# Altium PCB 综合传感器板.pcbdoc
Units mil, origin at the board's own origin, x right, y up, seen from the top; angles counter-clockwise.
Board outline 1885 x 1295 mil, 2 copper layers (Top Layer, Bottom Layer); 21 components, 15 nets, 74 pads, 12 vias.
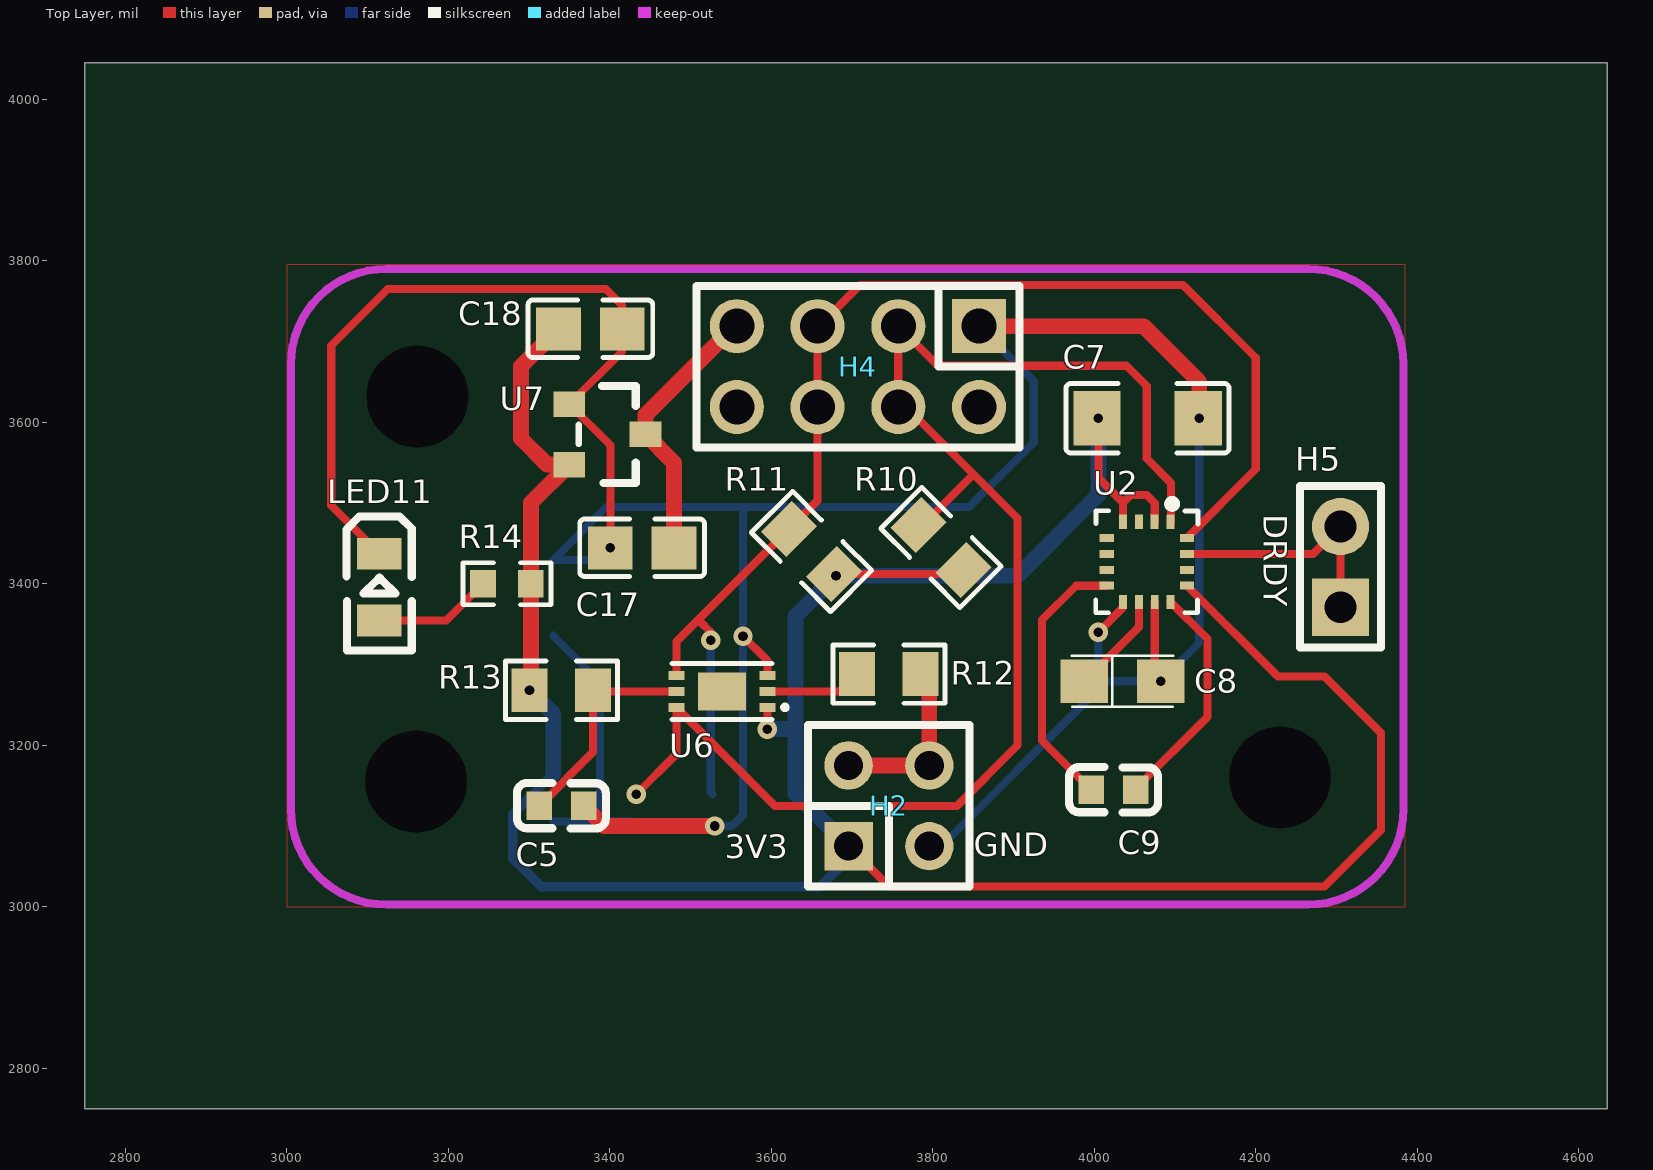
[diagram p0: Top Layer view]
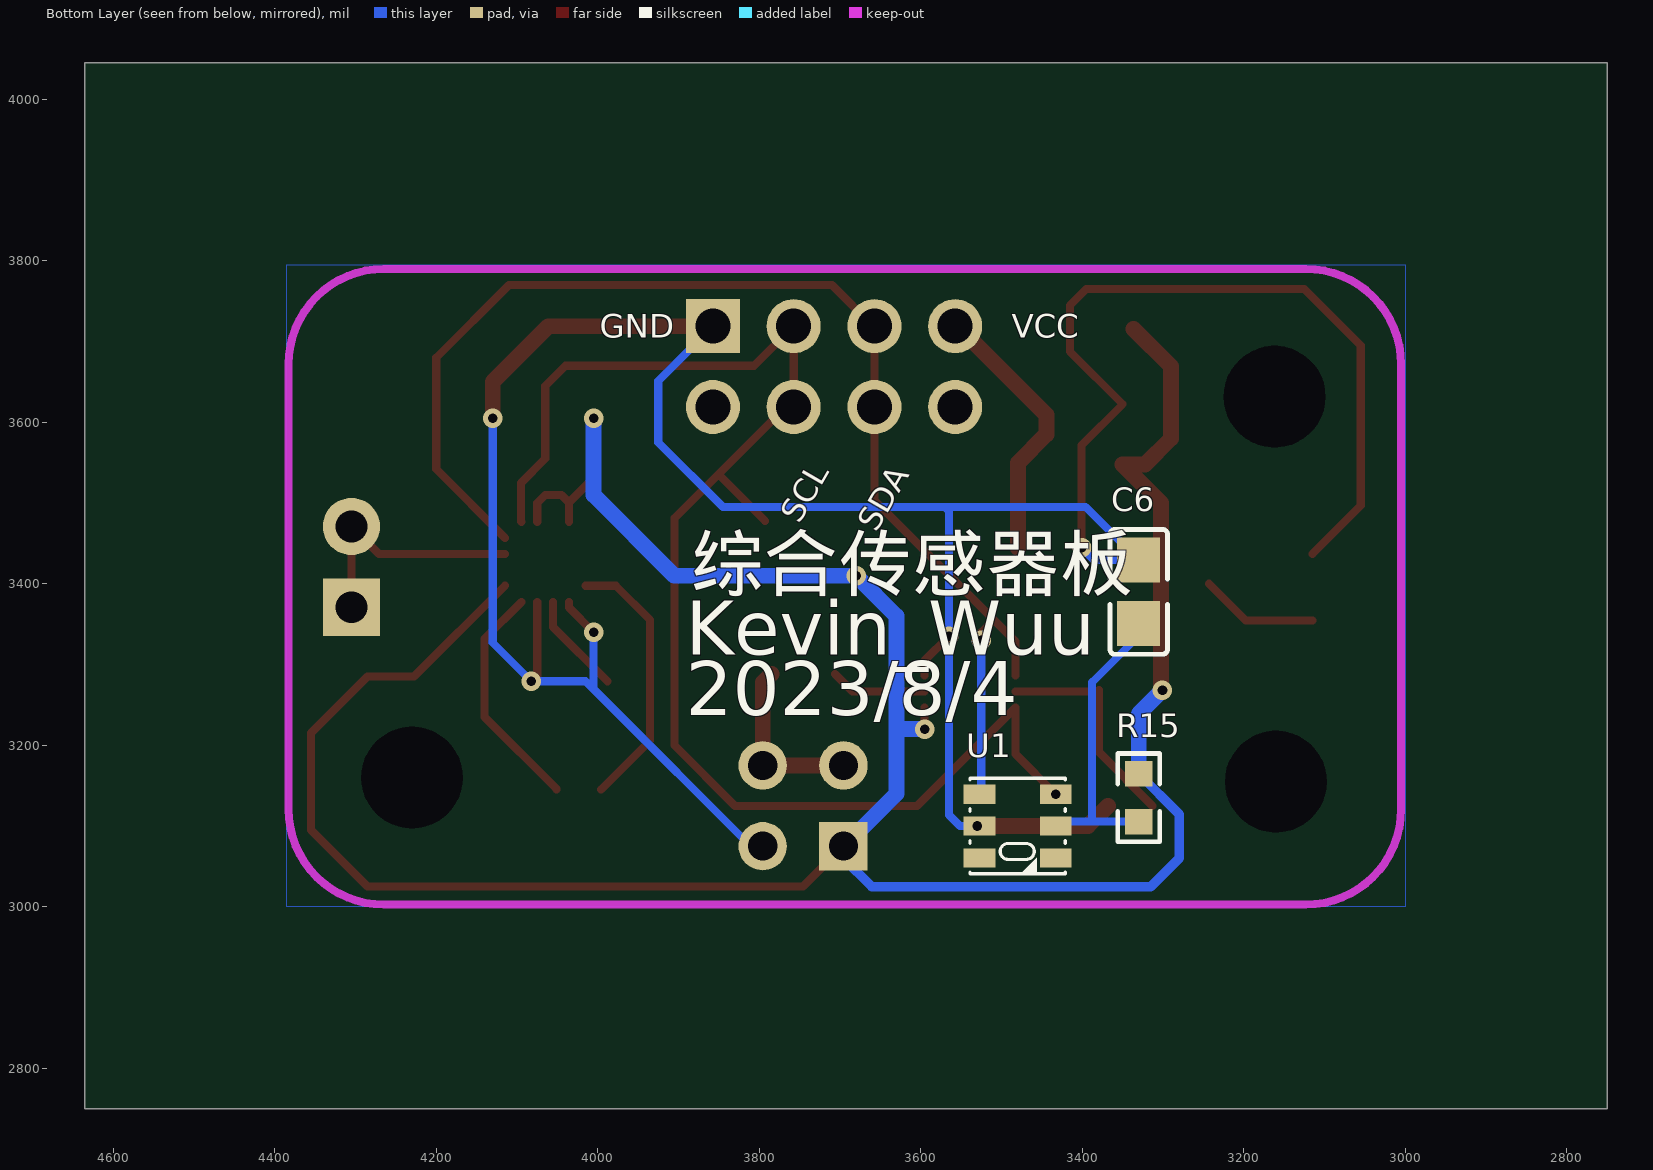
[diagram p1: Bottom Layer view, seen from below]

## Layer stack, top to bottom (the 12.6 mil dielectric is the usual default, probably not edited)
Top Layer: signal copper (thickness not stored)
Dielectric: dielectric 12.6, FR-4, Dk 4.8
Bottom Layer: signal copper (thickness not stored)

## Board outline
4635,2750 2750,2750 2750,4045 4635,4045
cut-out: 4292.99,3160 ccw(c4230,3160) 4167.01,3160 ccw(c4230,3160)
cut-out: 3222.99,3155 ccw(c3160,3155) 3097.01,3155 ccw(c3160,3155)
cut-out: 3224.74,3631.73 ccw(c3161.75,3631.73) 3098.76,3631.73 ccw(c3161.75,3631.73)

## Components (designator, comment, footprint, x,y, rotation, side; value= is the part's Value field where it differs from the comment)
C5 "CC0603KRX7R9BB104" C0603 3340.3,3125 r0 top
C6 "GRM21BR61H106KE43L" C0805 3330,3390 r90 bottom
C7 "1206B104K500AT" C1206 4065.99,3605 r0 top
C8 "TAJA475K016RNJ" CASE-A_3216 4035,3279.27 r0 top
C9 "CL10B224KA8NNNC" C0603 4023.55,3145 r180 top
C17 "CL21B105KBFNNNE" C0805 3440,3444.53 r180 top
C18 "CL21B105KBFNNNE" C0805 3375.94,3715.75 r0 top
H2 "HDR-M_2.54_2x2" HDR-TH_4P-P2.54-V-M-R2-C2-S2.54-1 3745.63,3125 r0 top
H4 "HDR-M_2.54_2x4" HDR-TH_8P-P2.54-V-M-R2-C4-S2.54 3707.24,3668.98 r180 top
H5 "HDR-M_2.54_1x2P" HDR-TH_2P-P2.54-V-M-1 4305,3420.99 r90 top
LED11 "NCD0805B2" LED0805-R-RD 3114.73,3395.8 r270 top
R10 "0805W8F4701T5E" R0805 3810,3445 r315 top
R11 "0805W8F4701T5E" R0805 3649.79,3440 r135 top
R12 "RMCF0805FT10K0" R0805 3745.63,3288.21 r0 top
R13 "0805W8F1001T5E" R0805 3340,3268.22 r180 top
R14 "0603WAF100KT5E" R0603 3272.62,3400 r0 top
R15 "0603WAF3600T5E" R0603 3330,3135.12 r270 bottom
U1 "AHT20-F" SENSOR-SMD-6_AHT20 3480,3100 r0 bottom
U2 "QMC5883L" LGA-16_L3.0-W3.0-P0.50-BL_SQ 4065,3427.15 r180 top
U6 "BH1750FVI-TR" WSOF-6_L2.6-W1.6-P0.50-TL-EP 3538.89,3266.62 r180 top
U7 "XC6206-3.3V" SSOT-3_L2.9-W1.6-P0.95-LS2.8-BR 3397.08,3585 r180 top

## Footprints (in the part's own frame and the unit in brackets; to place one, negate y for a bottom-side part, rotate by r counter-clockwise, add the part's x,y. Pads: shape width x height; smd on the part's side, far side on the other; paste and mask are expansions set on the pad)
C0603 [mm]
  rect 0.8x0.9 smd mask+0.051: 1(-0.7,0) 2(0.7,0)
  silkscreen extent -1.41,-0.71 1.39,0.72
C0805 [mm]
  rect 1.41x1.35 smd paste-100 mask+0.051: 1(-1,0) 2(1,0)
  silkscreen extent -1.96,-0.9 1.96,0.9
C1206 [mm]
  rect 1.485x1.728 smd paste-100 mask+0.051: 1(-1.593,0) 2(1.593,0)
  silkscreen extent -2.56,-1.09 2.56,1.09
CASE-A_3216 [mil]
  rect 59.05x53.5 smd mask+2.01: 1(-47.24,0) 2(47.24,0)
  silkscreen extent -63,-32 63,32
HDR-TH_2P-P2.54-V-M-1 [mm]
  rect 1.8x1.8 hole 1 mask+0.051: 1(-1.27,0)
  round 1.8 hole 1 mask+0.051: 2(1.27,0)
  silkscreen extent -2.54,-1.27 2.54,1.27
HDR-TH_4P-P2.54-V-M-R2-C2-S2.54-1 [mil]
  rect 60x60 hole 36 mask+2.01: 1(-50,-50)
  round 60 hole 36 mask+2.01: 2(-50,50) 3(50,-50) 4(50,50)
  silkscreen extent -100,-100 100,100
HDR-TH_8P-P2.54-V-M-R2-C4-S2.54 [mm]
  rect 1.7x1.7 hole 1.1 mask+0.051: 1(-3.81,-1.27)
  round 1.7 hole 1.1 mask+0.051: 2(-3.81,1.27) 3(-1.27,-1.27) 4(-1.27,1.27) 5(1.27,-1.27) 6(1.27,1.27) 7(3.81,-1.27) 8(3.81,1.27)
  silkscreen extent -5.08,-2.54 5.08,2.54
LED0805-R-RD [mm]
  rect 1x1.4 smd mask+0.051: 1(1.05,0) 2(-1.05,0)
  silkscreen extent -2.22,-1.04 1.99,1.01
LGA-16_L3.0-W3.0-P0.50-BL_SQ [mm]
  rect 0.25x0.45 smd mask+0.051: 1(-0.75,-1.263) 2(-0.25,-1.263) 3(0.25,-1.263) 4(0.75,-1.263) 9(0.75,1.263) 10(0.25,1.263) 11(-0.25,1.263) 12(-0.75,1.263)
  rect 0.45x0.25 smd mask+0.051: 5(1.263,-0.75) 6(1.263,-0.25) 7(1.263,0.25) 8(1.263,0.75) 13(-1.263,0.75) 14(-1.263,0.25) 15(-1.263,-0.25) 16(-1.263,-0.75)
  silkscreen extent -1.61,-1.95 1.61,1.6
R0603 [mil]
  rect 31.75x34.02 smd paste-3937.01 mask+2: 1(-29.66,0) 2(29.66,0)
  silkscreen extent -55,-26 55,26
R0805 [mm]
  rect 1.133x1.377 smd paste-100 mask+0.051: 1(-1,0) 2(1,0)
  silkscreen extent -1.76,-0.92 1.76,0.92
SENSOR-SMD-6_AHT20 [mm]
  rect 1x0.6 smd paste+0 mask+0.05: 1(-1.2,1) 2(-1.2,0) 3(-1.2,-1) 4(1.2,-1) 5(1.2,0) 6(1.2,1)
  silkscreen extent -1.5,-1.5 1.5,1.5
SSOT-3_L2.9-W1.6-P0.95-LS2.8-BR [mm]
  rect 1x0.8 smd mask+0.051: 1(1.2,-0.95) 2(1.2,0.95) 3(-1.2,0)
  silkscreen extent -0.89,-1.52 0.9,1.52
WSOF-6_L2.6-W1.6-P0.50-TL-EP [mm]
  rect 0.505x0.28 smd mask+0.051: 1(-1.427,0.5) 2(-1.427,0) 3(-1.427,-0.5) 4(1.427,-0.5) 5(1.427,0) 6(1.427,0.5)
  rect 1.5x1.2 smd mask+0.051: 7(0,0)
  silkscreen extent -2.05,-0.88 1.58,0.88

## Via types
v1: diameter 24.02, hole 12.01, Top Layer to Bottom Layer, 12 vias

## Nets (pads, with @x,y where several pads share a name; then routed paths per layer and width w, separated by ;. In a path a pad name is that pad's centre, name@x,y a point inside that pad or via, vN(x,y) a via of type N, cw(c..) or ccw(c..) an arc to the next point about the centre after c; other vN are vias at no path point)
$1N853: R12.1 U6.2 | length 120.1
  Top Layer w10: U6.2 3684.67,3266.61 R12.1
$1N861: C5.1 R13.1 U6.5 | length 274.8
  Top Layer w10: C5.1 3379.37,3191.62 R13.1@3379.37,3265.01 ; R13.1 R13.1@3379.37,3265.01 ; U6.5 3380.98,3266.61 R13.1@3379.37,3265.01
$1N1365: LED11.1 R14.1 | length 147.1
  Top Layer w10: LED11.1 3197.41,3354.45 R14.1
$1N1636: C6.1 R15.2 U1.2 | length 359.1
  Bottom Layer w10: R15.2 3387.6,3105.46 ; C6.1@3330,3335.63 3387.6,3278.03 3387.6,3105.46 ; U1.2 3427.3,3105.46 3387.6,3105.46
$1N2184: C8.1 U2.10 | length 126.1
  Top Layer w10: C8.1 4055.16,3346.68 U2.10
$1N2239: C9.1 U2.12 | length 288.1
  Top Layer w10: C9.1 4051.11,3146.11 4140,3235 4140,3331.96 U2.12
$1N2277: C9.2 U2.8 | length 333.2
  Top Layer w10: C9.2 3935,3205.99 3935,3355 3977.61,3397.61 U2.8
ADDR: H2.2 H2.4 R12.2 | length 217.6
  Top Layer w19.68: H2.2 H2.4 3795.63,3277.58 R12.2
BATT_MS: C17.1 H4.7 U7.3 | length 337.7
  Top Layer w19.68: C17.1 3479.37,3549.95 U7.3 3444.32,3609.32 3553.98,3718.98 H4.7
DRDY_MAG: H5.1 H5.2 U2.15 | length 304.4
  Top Layer w10: U2.15 4271,3436.99 H5.2 H5.1
GND_MS: C5.2 C6.2 C7.2 C8.2 C17.2 C18.2 H2.3 H4.1 LED11.2 U1.5 U2.9 U2.11 U6.3 U7.1 | length 3884.5
  Top Layer w10: LED11.2 3055,3496.88 3055,3695 3125,3765 3395,3765 3415.31,3744.69 C18.2 3415.31,3687.88 U7.1 3400.63,3571.61 v1(3400.63,3444.53) ; v1(3565,3335) 3595.09,3304.91 U6.3 ; v1(4005,3340) 4035.47,3370.47 U2.9 ; U2.11 4074.84,3286.67 v1(4082.24,3279.27)
  Top Layer w19.68: C5.2 3392.86,3100 v1(3530,3100) ; H4.1 4061.02,3718.98 4130,3650 4130,3606.31 C7.2
  Bottom Layer w10: v1(3400.63,3444.53) 3385.47,3429.37 C6.2 3395.63,3495 3570,3495 ; U1.5 3551.33,3100 3565,3113.67 v1(3565,3335) 3565,3490 3570,3495 ; H2.3@3795.63,3060 4006.01,3270.38 ; H4.1 3925,3651.22 3925,3575 3845,3495 3570,3495 ; v1(4005,3340) 4005,3271.39 4006.01,3270.38 ; v1(4130,3605) 4130,3327.03 v1(4082.24,3279.27) 4014.9,3279.27 4006.01,3270.38
SCL_MS: H4.3 H4.4 R10.1 U1.3 U2.1 U6.6 | length 1823.5
  Top Layer w10: v1(3432.76,3139.37) 3482.69,3189.3 U6.6 3604.63,3125 3830,3125 3905,3200 3905,3481.22 3850.61,3535.61 ; H4.3@3757.24,3728.98 H4.3 ; R10.1@3792.58,3477.58 3850.61,3535.61 ; U2.1 4095,3477.35 4095,3525 4065,3555 4065,3645 4040,3670 3806.22,3670 H4.3 ; H4.3 3757.24,3628.98 3850.61,3535.61
SDA_MS: H4.5 H4.6 R11.2 U1.4 U2.16 U6.4 | length 1599.4
  Top Layer w10: U6.4 3482.69,3328.57 3507.56,3353.44 ; v1(3525,3330) 3525,3340 3511.56,3353.44 3507.56,3353.44 ; H4.5@3657.24,3728.98 H4.5 ; U2.16 4200,3541.96 4200,3680 4110,3770 3710,3770 3658.98,3718.98 H4.5 ; 3507.56,3353.44 R11.2 3657.24,3503.12 H4.6 H4.5
  Bottom Layer w10: v1(3525,3330) 3525,3141.61 U1.4
VCC_3V3_2: C7.1 C18.1 H2.1 R10.2 R11.1 R13.2 R14.2 R15.1 U2.2 U2.4 U2.13 U6.1 U7.2 | length 3639.3
  Top Layer w10: v1(3595,3220) 3595.09,3220.09 U6.1 ; R11.1 3832.84,3412.16 R10.2 ; H2.1 3745.63,3025 4285,3025 4355,3095 4355,3215 4285,3285 4227.35,3285 U2.13 ; v1(4005,3605) 4005,3530.93 4035.47,3500.47 ; U2.4 4035.47,3500.47 ; U2.2 4074.84,3500.16 4065,3510 4045,3510 4035.47,3500.47
  Top Layer w19.68: v1(3300.63,3268.22) 3302.28,3269.88 R14.2 3302.28,3500.04 U7.2 3322.4,3547.6 3290,3580 3290,3669.18 C18.1
  Bottom Layer w11.81: R15.1 3280,3114.78 3280,3060 3315,3025 3660.63,3025 H2.1@3695.63,3060
  Bottom Layer w19.68: v1(3300.63,3268.22) 3330,3238.86 R15.1 ; v1(3595,3220) 3629.72,3220 3630,3219.72 ; H2.1 3695,3075 3630,3140 3630,3219.72 ; v1(4005,3605) 4005,3510 3905,3410 v1(3680,3410) 3630,3360 3630,3219.72
"": H4.2 H4.8 U1.1 U1.6 U2.3 U2.5 U2.6 U2.7 U2.14 U6.7

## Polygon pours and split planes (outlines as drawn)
GND_MS on Bottom Layer (solid, remove dead copper, pour order 0): 3000,3000 4385,3000 4385,3795 3000,3795
VCC_3V3_2 on Top Layer (solid, remove dead copper, pour order 1): 3000,3000 4385,3000 4385,3795 3000,3795

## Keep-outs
Board Outline Layer:
  lines w10 net "": 3005,3120.71 ccw(c3123.11,3120.71) 3123.11,3002.6 4264.84,3002.6 ccw(c4264.84,3120.71) 4382.95,3120.71 4382.95,3671.89 ccw(c4264.84,3671.89) 4264.84,3790 3123.11,3790 ccw(c3123.11,3671.89) 3005,3671.89 3005,3120.71

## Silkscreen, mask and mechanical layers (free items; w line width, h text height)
Top Silkscreen Layer:
  text "DRDY" at 4209.99,3486.08 h29.2 r270
  text "GND" at 3850.81,3062.49 h29.2
  text "3V3" at 3542.51,3059.99 h29.2
Bottom Silkscreen Layer:
  text "VCC" at 3487.51,3704.99 h29.2
  text "GND" at 3997.51,3704.99 h29.2
  text "SCL" at 3750.1,3472.84 h29.2 r300
  text "SDA" at 3655.1,3462.84 h29.2 r300
  text "综合传感器板" at 3885.58,3392.34 h66.9
  text "Kevin_Wuu" at 3891.08,3312.34 h66.9
  text "2023/8/4" at 3890.91,3237.34 h66.9
Mechanical Layer:
  circle w1 net "": c4230,3160 r62.99
  circle w1 net "": c3160,3155 r62.99
  circle w1 net "": c3161.75,3631.73 r62.99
